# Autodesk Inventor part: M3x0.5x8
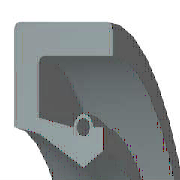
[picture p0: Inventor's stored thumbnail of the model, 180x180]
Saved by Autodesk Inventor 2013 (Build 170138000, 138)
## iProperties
Company: 한국ATC센터
IsCustomPart: 1
Created: 2009-02
Part Number: M3x0.5x8
Material: 고무
Description: 오일-실
Document SubType Name: Modeling
Standard: KS B 2804
Designer: KYOUNG IL JANG
Standards Organization: KS
Language: ko-KR
Size Designation: S - 12 22 7
Categories: <MemberInstance><Categories><Category DisplayName="샤프트 부품" InternalName="7f7aeb1f-a693-4053-b835-cee3144e0d98" Mnemonic="SHFT"><Category DisplayName="실링" Intern
Density: 0.93 g/cm^3
Mass: 1.0258 g
Surface Area: 17.5559 cm^2
Volume: 1.10301 cm^3
Vendor: CBT Solutions
Author: KYOUNG IL JANG
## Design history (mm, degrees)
revolve "본체" stored, may be unused: angle "d17" = 90 deg
revolve "스프링1" stored, may be unused: angle "d18" = 90 deg
body "Solid1"
sketch "스케치1"
  geometry: L1 (0, 11)-(7, 11); L2 (7, 11)-(7, 9.75); L3 (7, 9.75)-(1.75, 9.75); L4 (0, 11)-(0, 8.1); L5 (0, 8.1)-(1.75, 7.75); L6 (1.75, 7.75)-(4.9, 6); L7 (4.9, 6)-(0, 6); L8 (6.3, 6.875)-(6.3, 8.1); L9 (0, 0)-(9.586, 0) reference; L10 (4.9, 6)-(6.3, 6.875); L11 (0, 18)-(0, -3) reference; L12 (-1.917, 0)-(11.503, 0) reference; L13 (4.2, 8.1)-(1.75, 8.59); L14 (1.75, 8.59)-(1.75, 9.75); L15 (6.3, 8.1)-(5.6, 8.1); C1 r 0.455 at (4.9, 8.1); A1 r 0.7 centre (4.9, 8.1) between (5.6, 8.1) and (4.2, 8.1)
  constraints: 26 end point, 5 horizontal alignment, 4 perpendicular, 2 centre point, 2 collinear, 2 horizontal, 2 parallel, 2 point on circle, 2 point on line, 2 vertical alignment, 1 coincident
  dimensions: "d0" = 22 diameter of L1 L9 (= SD2); "d1" = 13.75 diameter of L8.start L9 (= ABDM); "d2" = 1.25 distance of L1.end L2.end (computed from SD); "d3" = 0.91 diameter of C1 (= SPDI); "d4" = 1.4 diameter of A1 (= SPDA); "d5" = 12 diameter of L6.end L9 (= NND); "d6" = 15.5 diameter of L5.end L9 (= TKDM); "d7" = 16.2 diameter of L4.end L9 (= HLDM); "d8" = 4.9 distance from line of C1.centre L4 (= SPDST); "d9" = 6.3 distance between parallel lines of L8 L4 (= SDI); "d10" = 7 distance between parallel lines of L2 L4 (= SWDT); "d12" = 1.75 distance between parallel lines of L14 L4 (= SD)
fillet "모깎기1" dims "d11" = 0.3 (= RR)
other parameters: "SD2" = 22 [user parameter; used in 1 equation term], "SWDT" = 7 [user parameter; used in 1 equation term], "RR" = 0.3 [user parameter; used in 1 equation term], "SD" = 1.75 [user parameter; used in 2 equation terms], "NND" = 12 [user parameter; used in 1 equation term], "SPDA" = 1.4 [user parameter; used in 1 equation term], "SPDI" = 0.91 [user parameter; used in 1 equation term], "TKDM" = 15.5 [user parameter; used in 1 equation term], "HLDM" = 16.2 [user parameter; used in 1 equation term], "ABDM" = 13.75 [user parameter; used in 1 equation term], "SDI" = 6.3 [user parameter; used in 1 equation term], "SPDST" = 4.9 [user parameter; used in 1 equation term], "d13" = 0, "d14" = 0, "d15" = 0, "LAB" = 0.35 [user parameter]
